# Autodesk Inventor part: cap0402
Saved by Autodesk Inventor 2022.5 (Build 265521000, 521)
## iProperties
Created: 2024-12
Part Number: cap0402
Material: Generic
Document SubType Name: Modeling
Designer: AdminForWorker
Density: 1 g/cm^3
Appearance: Default
Title: cap0402 v1
Author: AdminForWorker
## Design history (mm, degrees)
feature "Body6"
feature "Body8"
feature "Body18"
body "Solid1"
body "Solid2"
body "Solid3"
